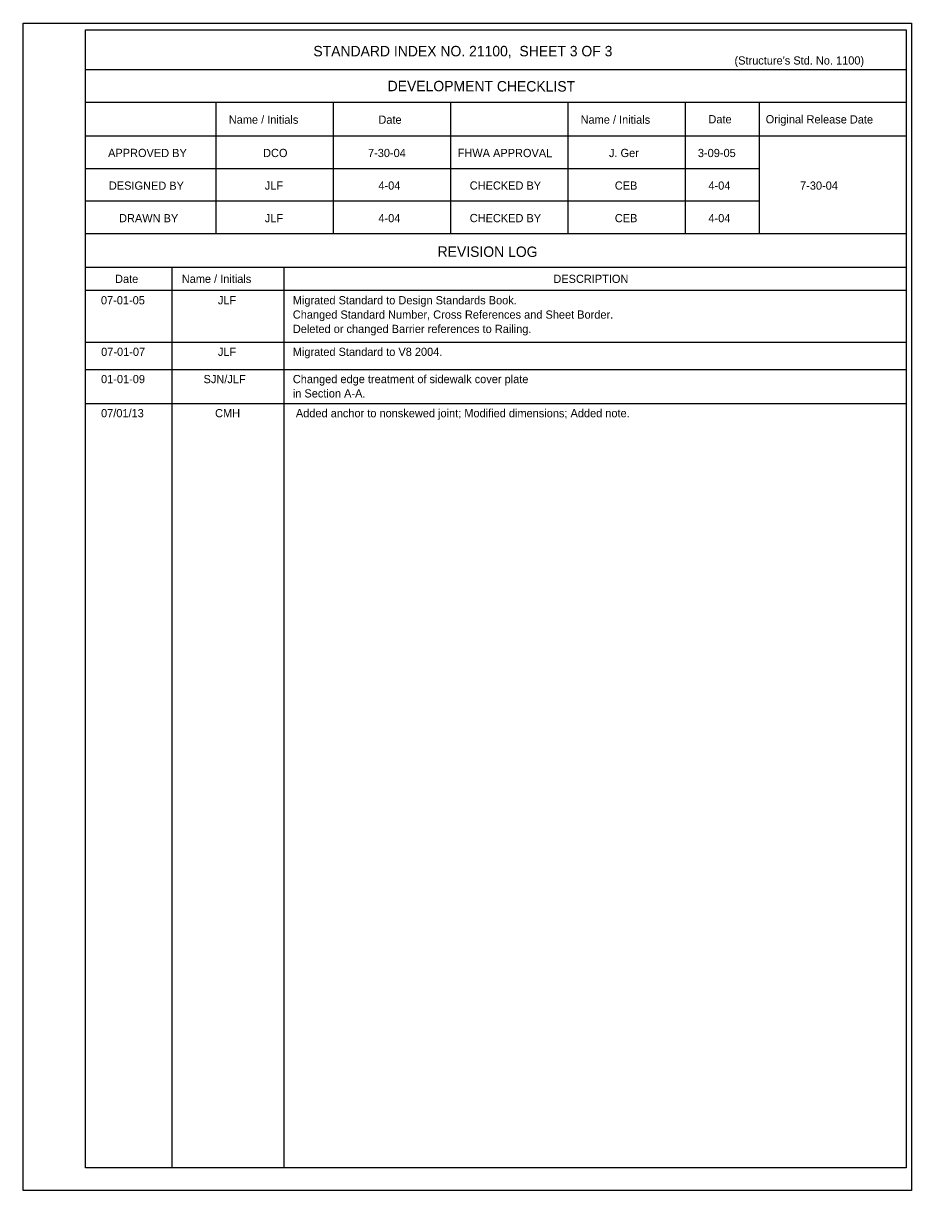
# Model space of a CAD drawing. Extents: x 106275.7 to 106302.2, y 131.6 to 145.8.
# Drawn here: x 106294.03 to 106302.21, y 133.78 to 144.53 of the extents above; entities that cross this region are included whole.
import ezdxf

# ---------------------------------------------------------------- set-up
doc = ezdxf.new("R2010")
doc.units = 0
for name, color, linetype in [('Border', 7, 'Continuous'), ('Dimension', 7, 'Continuous'), ('PlotBorder_dp', 7, 'Continuous'), ('TextStructures', 7, 'Continuous')]:
    doc.layers.add(name, color=color, linetype=linetype)

msp = doc.modelspace()

# ---------------------------------------------------------------- linework, layer by layer
at = {"layer": 'Border'}
for p, q in [((106302.156, 144.106), (106294.601, 144.106)), ((106302.156, 143.806), (106294.601, 143.806)), ((106295.801, 143.806), (106295.801, 142.596)), ((106296.881, 143.806), (106296.881, 142.596)), ((106297.961, 143.806), (106297.961, 142.596)), ((106299.041, 143.806), (106299.041, 142.596)), ((106300.121, 143.806), (106300.121, 142.596)), ((106300.802, 143.806), (106300.802, 142.596)), ((106302.156, 143.496), (106294.601, 143.496)), ((106300.802, 143.196), (106294.601, 143.196)), ((106300.802, 142.896), (106294.601, 142.896)), ((106302.156, 142.596), (106294.601, 142.596)), ((106302.156, 142.285), (106294.601, 142.285)), ((106295.396, 142.285), (106295.396, 133.995)), ((106296.425, 142.285), (106296.425, 133.995)), ((106302.156, 142.074), (106294.601, 142.074))]:
    msp.add_line(p, q, dxfattribs=at)
msp.add_lwpolyline([(106294.601, 144.474), (106302.156, 144.474), (106302.156, 133.995), (106294.601, 133.995)], close=True, dxfattribs=at)
at = {"layer": 'Dimension'}
for p, q in [((106294.601, 141.599), (106302.156, 141.599)), ((106294.601, 141.348), (106302.156, 141.348)), ((106294.601, 141.033), (106302.156, 141.033))]:
    msp.add_line(p, q, dxfattribs=at)
at = {"layer": 'PlotBorder_dp'}
msp.add_line((106294.027, 133.785), (106294.027, 133.785), dxfattribs=at)
msp.add_lwpolyline([(106294.027, 144.535), (106302.207, 144.535), (106302.207, 133.785), (106294.027, 133.785)], close=True, dxfattribs=at)

# ---------------------------------------------------------------- texts
at = {"layer": 'TextStructures'}
for s, height, p in [('STANDARD INDEX NO. 21100,  SHEET 3 OF 3', 0.096, (106296.698, 144.231)), ("(Structure's Std. No. 1100)", 0.0756, (106300.576, 144.155)), ('DCO', 0.0756, (106296.235, 143.303)), ('7-30-04', 0.0756, (106297.201, 143.303)), ('J. Ger', 0.0756, (106299.42, 143.303)), ('3-09-05', 0.0756, (106300.239, 143.303)), ('JLF', 0.0756, (106296.251, 143.003)), ('4-04', 0.0756, (106297.297, 143.003)), ('CEB', 0.0756, (106299.474, 143.003)), ('4-04', 0.0756, (106300.336, 143.003)), ('7-30-04', 0.0756, (106301.18, 143.003)), ('JLF', 0.0756, (106296.251, 142.703)), ('4-04', 0.0756, (106297.297, 142.703)), ('CEB', 0.0756, (106299.474, 142.703)), ('4-04', 0.0756, (106300.336, 142.703)), ('DESCRIPTION', 0.0756, (106298.908, 142.144)), ('07-01-05', 0.0756, (106294.742, 141.947)), ('JLF', 0.0756, (106295.819, 141.947)), ('Migrated Standard to Design Standards Book.', 0.0756, (106296.509, 141.947)), ('Changed Standard Number, Cross References and Sheet Border.', 0.0756, (106296.509, 141.815)), ('Deleted or changed Barrier references to Railing.', 0.0756, (106296.509, 141.683)), ('07-01-07', 0.0756, (106294.744, 141.472)), ('JLF', 0.0756, (106295.819, 141.472)), ('Migrated Standard to V8 2004.', 0.0756, (106296.509, 141.472)), ('01-01-09', 0.0756, (106294.743, 141.221)), ('SJN/JLF', 0.0756, (106295.687, 141.221)), ('Changed edge treatment of sidewalk cover plate ', 0.0756, (106296.509, 141.221)), ('in Section A-A.', 0.0756, (106296.509, 141.089)), ('07/01/13', 0.0756, (106294.743, 140.907)), ('CMH', 0.0756, (106295.793, 140.907)), (' Added anchor to nonskewed joint; Modified dimensions; Added note.  ', 0.0756, (106296.509, 140.907))]:
    msp.add_text(s, height=height, dxfattribs=at).set_placement(p)
for s, height, p in [('DEVELOPMENT CHECKLIST', 0.096, (106297.382, 143.91)), ('Name / Initials', 0.0756, (106295.919, 143.611)), ('Date', 0.0756, (106297.297, 143.61)), ('Name / Initials', 0.0756, (106299.159, 143.611)), ('Date', 0.0756, (106300.336, 143.614)), ('Original Release Date', 0.0756, (106300.863, 143.614)), ('APPROVED BY', 0.0756, (106294.808, 143.304)), ('FHWA APPROVAL', 0.0756, (106298.027, 143.304)), ('DESIGNED BY', 0.0756, (106294.815, 143.003)), ('CHECKED BY', 0.0756, (106298.138, 143.004)), ('DRAWN BY', 0.0756, (106294.909, 142.703)), ('CHECKED BY', 0.0756, (106298.138, 142.704)), ('REVISION LOG', 0.096, (106297.842, 142.385)), ('Name / Initials', 0.0756, (106295.486, 142.145)), ('Date', 0.0756, (106294.872, 142.144))]:
    msp.add_text(s, height=height, rotation=359.8756, dxfattribs=at).set_placement(p)

doc.saveas('drawing.dxf')
